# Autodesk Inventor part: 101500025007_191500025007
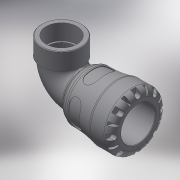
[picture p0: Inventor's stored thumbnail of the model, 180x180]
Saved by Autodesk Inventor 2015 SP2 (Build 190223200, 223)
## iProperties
Created: 2016-12
Part Number: 101500025007_191500025007
Material: Generic
Description: PLASSON 90° ELBOW WITH THREADED FEMALE OFFTAKE 25X3/4" SERIES 1
Document SubType Name: Modeling
Designer: KIM
Mass: 557.611 g
Surface Area: 990.043 cm^2
Volume: 557.611 cm^3
Density: 1 g/cm^3
Appearance: Default
Author: KIM
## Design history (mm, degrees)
derived "1015.ipt"
feature "Solid1::1015.ipt"
tag "TaggingFeature1"
body "Solid1"
other parameters: "d1" = 20.16, "d2" = 25, "d3" = 31.25, "d4" = 47, "d8" = 41.36, "d13" = 6.3, "d14" = 6.3, "d15" = 0, "d17" = 360 deg, "d19" = 8 deg, "d20" = 0.5, "d21" = 0.5, "d22" = 8 deg, "d24" = 0, "d26" = 360 deg, "d33" = 4.7, "d43" = 38.54, "d51" = 0.47, "d54" = 8.75, "d55" = 5.5, "d57" = 12.348, "d58" = 0, "d74" = 0, "d78" = 48, "d82" = 0.5, "d115" = 360 deg, "d207" = 90 deg, "d228" = 7.4375, "d247" = 0.94, "d248" = 2.88, "d268" = 22.748, "d269" = 2.88, "d270" = 74, "d279" = 43, "d281" = 3.61755, "d294" = 24.117, "d295" = 18, "d296" = 19.8, "d297" = 21.7053, "d299" = 28.21689, "d300" = 21.7053, "d301" = 0, "d302" = 0, "d303" = 5.16155, "d306" = 0, "d307" = 9, "d308" = 8, "d310" = 3, "d_" = 25, "E_" = 47, "l_" = 48, "A_" = 74, "A_1" = 43, "l_2" = 18, "Rp_" = 24.117, "d9" = 7.875, "d11" = 47, "d12" = 31.25, "d298" = 31.3521
